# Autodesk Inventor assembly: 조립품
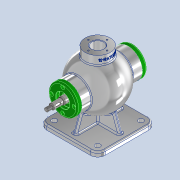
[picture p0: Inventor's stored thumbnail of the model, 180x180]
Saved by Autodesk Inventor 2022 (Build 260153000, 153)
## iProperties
Created: 2024-04
Part Number: 조립품
Document SubType Name: Assembly
Designer: Admin
Author: Admin
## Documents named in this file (8)
- C:\Users\Admin\Desktop\740406V1014\조립품.iam
- C:\Users\Admin\Desktop\740406V1014\본체.ipt
- C:\Users\Admin\Desktop\740406V1014\편심축.ipt
- C:\Users\Admin\Desktop\740406V1014\칼라.ipt
- C:\Users\Admin\Desktop\740406V1014\베어링- 6202.ipt
- KS B 2023 - 6202 - 15 x 35 x 11 - 7.8.ipt
- C:\Users\Admin\Desktop\740406V1014\앞커버.ipt
- C:\Users\Admin\Desktop\740406V1014\뒤커버.ipt
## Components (2 placed, 1 different names)
1. KS B 2023 - 6202 - 15 x 35 x 11 - 7.8:1
2. KS B 2023 - 6202 - 15 x 35 x 11 - 7.8:2
